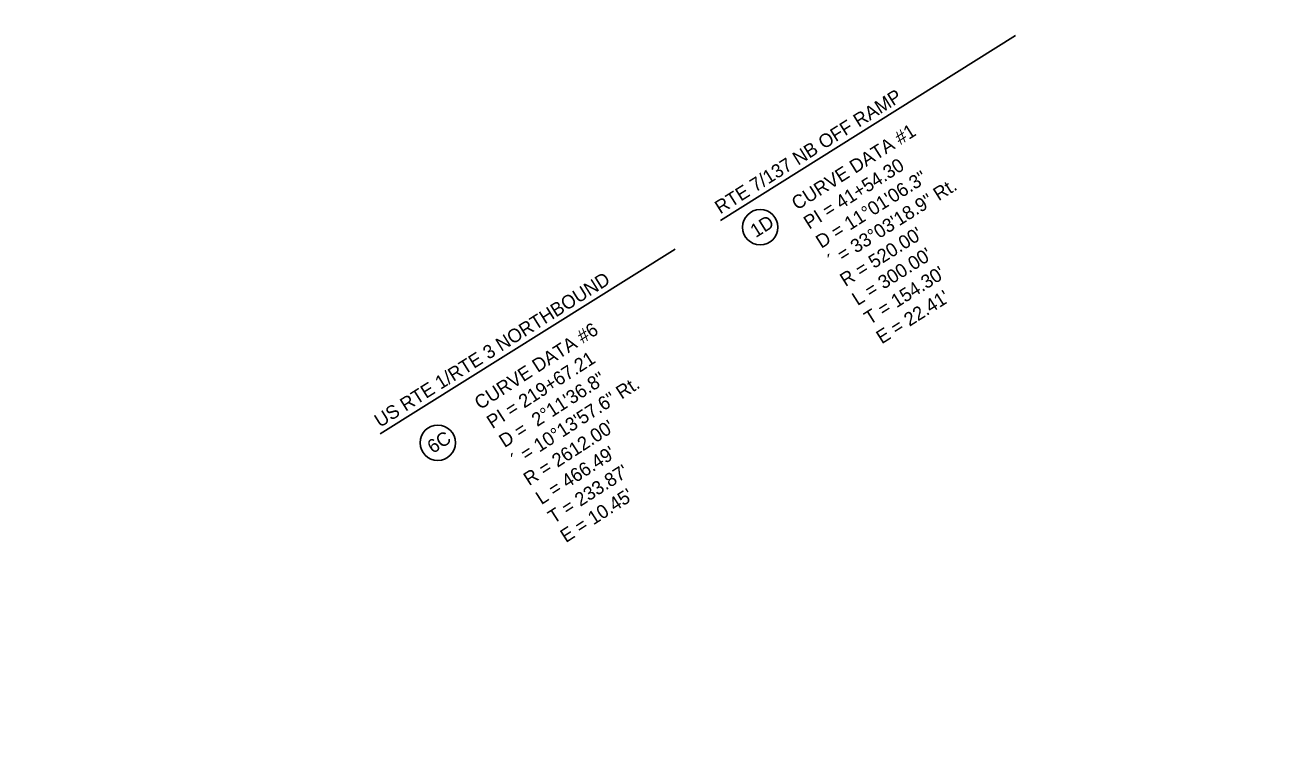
# Model space of a CAD drawing. Extents: x 1667099 to 1669772, y 337408 to 340124.
# Drawn here: x 1668291.9 to 1668570.7, y 339149.8 to 339309.5 of the extents above; entities that cross this region are included whole.
import ezdxf

# ---------------------------------------------------------------- set-up
doc = ezdxf.new("R2010")
doc.units = 0
for name, color, linetype in [('Alignment', 7, 'Continuous'), ('ANNOTATION', 7, 'Continuous'), ('D_Roadway_Centerline', 7, 'Continuous'), ('D_Roadway_Centerline_CurveData', 7, 'Continuous'), ('S_Roadway_Edge_Pavement', 7, 'Continuous')]:
    doc.layers.add(name, color=color, linetype=linetype)

msp = doc.modelspace()

# ---------------------------------------------------------------- linework, layer by layer
at = {"layer": 'Alignment'}
msp.add_arc((1669829.28, 337256.22), 2612, 123.30352, 133.53618, dxfattribs=at)
at = {"layer": 'ANNOTATION'}
for p, q in [((1668445.57, 339266.34), (1668510.74, 339307.2)), ((1668370.33, 339219.16), (1668435.5, 339260.02))]:
    msp.add_line(p, q, dxfattribs=at)
for centre in [(1668454.33, 339264.85), (1668383.07, 339217.19)]:
    msp.add_circle(centre, 3.9, dxfattribs=at)
at = {"layer": 'D_Roadway_Centerline'}
for centre, radius, start, end in [((1669819.48, 337273.8), 2613, 114.83733, 133.776), ((1669829.28, 337256.22), 2612, 123.30352, 133.53618)]:
    msp.add_arc(centre, radius, start, end, dxfattribs=at)
at = {"layer": 'S_Roadway_Edge_Pavement'}
msp.add_arc((1669819.48, 337273.8), 2613, 114.83733, 133.776, dxfattribs=at)

# ---------------------------------------------------------------- texts
at = {"layer": 'ANNOTATION'}
for s, rotation, p in [('RTE 7/137 NB OFF RAMP', 32.0893, (1668445.51, 339267.65)), ('1D', 32.0893, (1668453.35, 339262.44)), ('US RTE 1/RTE 3 NORTHBOUND', 32.0893, (1668370.27, 339220.47)), ('6C', 32.5529, (1668381.98, 339214.7))]:
    msp.add_text(s, height=3, rotation=rotation, dxfattribs=at).set_placement(p)
at = {"layer": 'D_Roadway_Centerline_CurveData'}
for s, rotation, p in [('CURVE DATA #1', 32.3078, (1668462.48, 339268.52)), ('PI = 41+54.30', 32.3078, (1668465.15, 339264.29)), ('D = 11%%d01\'06.3"', 32.3078, (1668467.83, 339260.06)), ('´ = 33%%d03\'18.9" Rt.', 32.3078, (1668470.5, 339255.84)), ("R = 520.00'", 32.3078, (1668473.17, 339251.61)), ("L = 300.00'", 32.3078, (1668475.84, 339247.39)), ("T = 154.30'", 32.3078, (1668478.52, 339243.16)), ("E = 22.41'", 32.3078, (1668481.19, 339238.93)), ('CURVE DATA #6', 32.814, (1668392.42, 339224.4)), ('PI = 219+67.21', 32.814, (1668395.13, 339220.2)), ('D =  2%%d11\'36.8"', 32.814, (1668397.83, 339216)), ('´ = 10%%d13\'57.6" Rt.', 32.814, (1668400.54, 339211.79)), ("R = 2612.00'", 32.814, (1668403.25, 339207.59)), ("L = 466.49'", 32.814, (1668405.96, 339203.39)), ("T = 233.87'", 32.814, (1668408.67, 339199.19)), ("E = 10.45'", 32.814, (1668411.38, 339194.99))]:
    msp.add_text(s, height=3, rotation=rotation, dxfattribs=at).set_placement(p)

doc.saveas('drawing.dxf')
